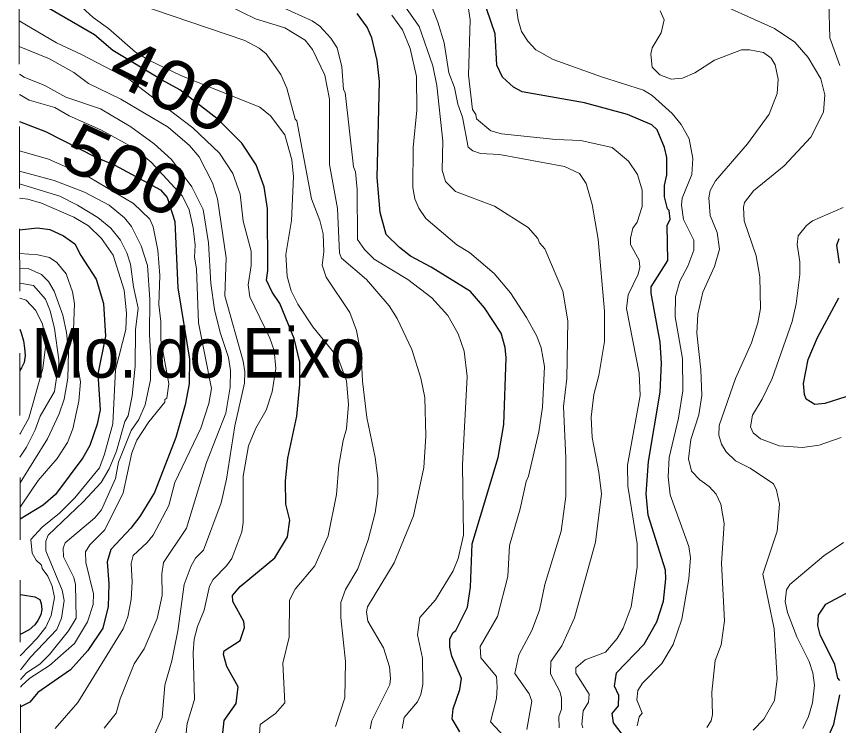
# Model space of a CAD drawing. Extents: x 474.5 to 500, y 7345.7 to 7373.4.
# Drawn here: x 474.522 to 475.844, y 7369.706 to 7370.847 of the extents above; entities that cross this region are included whole.
import ezdxf
from ezdxf.enums import TextEntityAlignment as Align

# ---------------------------------------------------------------- set-up
doc = ezdxf.new("R2010")
doc.units = 0
doc.header["$LTSCALE"] = 0.032
doc.linetypes.add('SHORT_DASHED', pattern=[2.7, 1.5, -1.2])
for name, color, linetype, lineweight in [('1', 7, 'Continuous', 25), ('2', 7, 'Continuous', 13), ('22', 7, 'SHORT_DASHED', 13)]:
    doc.layers.add(name, color=color, linetype=linetype, lineweight=lineweight)
doc.layers.add('61', color=7, linetype='Continuous')

msp = doc.modelspace()

# ---------------------------------------------------------------- linework, layer by layer
at = {"layer": '1'}
for points in [[(475.5426, 7370.4117), (475.5696, 7370.4544), (475.5681, 7370.5105), (475.5729, 7370.5208), (475.5713, 7370.5348), (475.5687, 7370.5375), (475.5641, 7370.5566), (475.5641, 7370.5748), (475.568, 7370.592), (475.568, 7370.62), (475.5639, 7370.6362), (475.5522, 7370.6644), (475.5439, 7370.6724), (475.5045, 7370.689), (475.4353, 7370.7078), (475.3351, 7370.7253), (475.321, 7370.7331), (475.3035, 7370.749), (475.2947, 7370.7685), (475.292, 7370.8186), (475.2434, 7370.9602)], [(474.8533, 7369.6894), (474.8564, 7369.7143), (474.8756, 7369.7417), (474.8785, 7369.7685), (474.8602, 7369.8014), (474.8549, 7369.8207), (474.8562, 7369.8265), (474.8819, 7369.843), (474.889, 7369.8642), (474.888, 7369.8738), (474.8701, 7369.906), (474.8697, 7369.9156), (474.8818, 7369.9299), (474.9376, 7369.976), (474.9579, 7370.01), (474.9618, 7370.0365), (474.9554, 7370.0626), (474.9548, 7370.0997), (474.9584, 7370.1361), (474.9731, 7370.204), (474.9777, 7370.2547), (474.9777, 7370.2908), (474.9685, 7370.3286), (474.9457, 7370.3849), (474.9334, 7370.4032), (474.9244, 7370.4227), (474.9265, 7370.4382), (474.9258, 7370.5381), (474.9204, 7370.5726), (474.9074, 7370.6083), (474.8846, 7370.6429), (474.8463, 7370.6808), (474.7848, 7370.729), (474.7566, 7370.7445), (474.6772, 7370.7919), (474.6478, 7370.817), (474.5266, 7370.8881)], [(475.2352, 7369.6964), (475.2227, 7369.7173), (475.2245, 7369.7333), (475.2351, 7369.7644), (475.2377, 7369.7818), (475.2223, 7369.8179), (475.2187, 7369.8323), (475.2187, 7369.8458), (475.224, 7369.856), (475.2283, 7369.8592), (475.2474, 7369.8967), (475.2522, 7369.929), (475.2546, 7369.9988), (475.2965, 7370.1376), (475.3055, 7370.1903), (475.3096, 7370.2976), (475.308, 7370.3144), (475.3016, 7370.3374), (475.2747, 7370.378), (475.2521, 7370.4046), (475.1889, 7370.4438), (475.1559, 7370.4613), (475.1378, 7370.475), (475.1164, 7370.496), (475.1069, 7370.5317), (475.1019, 7370.5877), (475.1061, 7370.7423), (475.1023, 7370.7758), (475.0933, 7370.8125), (475.0862, 7370.8298), (475.0701, 7370.8513)], [(474.527, 7370.6777), (474.5688, 7370.6619), (474.6497, 7370.6203), (474.6806, 7370.6076), (474.754, 7370.5678), (474.7644, 7370.5554), (474.7767, 7370.5171), (474.7814, 7370.4102), (474.8006, 7370.2956), (474.7997, 7370.2557), (474.7935, 7370.2222), (474.7784, 7370.1695), (474.7439, 7370.0813), (474.7204, 7370.0426), (474.7063, 7370.0238), (474.6739, 7369.9897), (474.6683, 7369.9698), (474.6706, 7369.9344), (474.6698, 7369.8977), (474.6609, 7369.8628), (474.6367, 7369.8272), (474.6091, 7369.7959), (474.5568, 7369.7594), (474.5437, 7369.7441), (474.5286, 7369.7362)], [(474.5273, 7370.5038), (474.5559, 7370.5067), (474.5759, 7370.5043), (474.5977, 7370.4941), (474.6162, 7370.4811), (474.6255, 7370.4622), (474.6506, 7370.4245), (474.662, 7370.3849), (474.6651, 7370.3327), (474.6531, 7370.2716), (474.657, 7370.214), (474.6519, 7370.1909), (474.6402, 7370.1565), (474.6287, 7370.1367), (474.585, 7370.0781), (474.565, 7370.061), (474.528, 7370.0382)], [(475.8455, 7370.4498), (475.841, 7370.4788), (475.845, 7370.4897)], [(475.5027, 7369.6832), (475.4818, 7369.7104), (475.4797, 7369.7257), (475.49, 7369.7381), (475.4907, 7369.7547), (475.4837, 7369.7697), (475.4866, 7369.7912), (475.5311, 7369.8372), (475.5516, 7369.8732), (475.5622, 7369.9063), (475.5664, 7369.9424), (475.5656, 7369.9562), (475.5378, 7370.0445), (475.5346, 7370.0792), (475.5385, 7370.1309), (475.5569, 7370.2423), (475.5593, 7370.2893), (475.5569, 7370.3227), (475.5426, 7370.4019), (475.5426, 7370.4117)], [(475.8555, 7370.2348), (475.822, 7370.2244), (475.8056, 7370.2229), (475.792, 7370.2311), (475.789, 7370.2389), (475.7875, 7370.2565), (475.7952, 7370.2952), (475.8097, 7370.3302), (475.844, 7370.394)], [(474.5276, 7370.3439), (474.5298, 7370.3379), (474.5338, 7370.3252), (474.5351, 7370.3131), (474.5361, 7370.3014), (474.5348, 7370.2904), (474.5304, 7370.2814), (474.5277, 7370.2773)], [(475.8457, 7369.7788), (475.8426, 7369.7826), (475.8376, 7369.8042), (475.8145, 7369.852), (475.8107, 7369.8674), (475.8115, 7369.8839), (475.8234, 7369.9013), (475.9077, 7369.9465)], [(474.5283, 7369.9171), (474.5318, 7369.9165), (474.5515, 7369.9132), (474.5599, 7369.9088), (474.5619, 7369.9025), (474.5629, 7369.8931), (474.5612, 7369.8841), (474.5565, 7369.8754), (474.5519, 7369.868), (474.5428, 7369.8603), (474.5291, 7369.853), (474.5284, 7369.8526)], [(475.8285, 7369.6916), (475.8362, 7369.7084), (475.8457, 7369.7557)]]:
    msp.add_lwpolyline(points, dxfattribs=at)
at = {"layer": '2'}
for points in [[(475.1774, 7370.8947), (475.1996, 7370.8375), (475.2098, 7370.8045), (475.2172, 7370.7561), (475.2266, 7370.7324), (475.2316, 7370.7057), (475.2395, 7370.6848), (475.2482, 7370.6368), (475.2558, 7370.6307), (475.268, 7370.6264), (475.2987, 7370.6247), (475.4035, 7370.6057), (475.4276, 7370.5944), (475.4379, 7370.578), (475.4476, 7370.5445), (475.4572, 7370.4886), (475.4675, 7370.3725), (475.4675, 7370.324), (475.4586, 7370.2692), (475.4506, 7370.2385), (475.4461, 7370.2021), (475.4476, 7370.1695), (475.4587, 7370.1137), (475.4627, 7370.0789), (475.4531, 7370.0012), (475.4191, 7369.8794), (475.3989, 7369.8343), (475.3812, 7369.8093), (475.3807, 7369.7896), (475.3956, 7369.7611), (475.3982, 7369.7507), (475.3982, 7369.7327), (475.3942, 7369.7209), (475.3949, 7369.7028)], [(475.3208, 7370.8982), (475.3287, 7370.8412), (475.3341, 7370.8224), (475.3442, 7370.8068), (475.3572, 7370.7933), (475.3849, 7370.7778), (475.4625, 7370.7496), (475.5301, 7370.7283), (475.5441, 7370.7197), (475.5764, 7370.6907), (475.5906, 7370.6732), (475.6038, 7370.6498), (475.6095, 7370.6182), (475.608, 7370.5926), (475.5924, 7370.5547), (475.5913, 7370.5433), (475.5948, 7370.52), (475.6111, 7370.4867), (475.6111, 7370.4709), (475.6014, 7370.4451), (475.5888, 7370.4211), (475.5815, 7370.3965), (475.5809, 7370.3637), (475.5929, 7370.2967), (475.5937, 7370.2446), (475.5864, 7370.2009), (475.5713, 7370.1376), (475.5697, 7370.1063), (475.5733, 7370.0771), (475.6031, 7369.994), (475.6056, 7369.9758), (475.6031, 7369.9422), (475.5921, 7369.8776), (475.5782, 7369.8369), (475.5597, 7369.806), (475.5284, 7369.7745), (475.5209, 7369.7625), (475.5195, 7369.7477), (475.5283, 7369.7261), (475.5235, 7369.7203), (475.5202, 7369.706)], [(475.8456, 7370.7678), (475.8297, 7370.8125), (475.8282, 7370.8693), (475.8256, 7370.8728), (475.8233, 7370.8942)], [(474.9125, 7369.684), (474.914, 7369.708), (474.9384, 7369.7256), (474.9537, 7369.7426), (474.9507, 7369.8065), (474.9604, 7369.8483), (474.9611, 7369.9079), (474.9701, 7369.9256), (475.0019, 7369.9632), (475.0233, 7370.0116), (475.0367, 7370.0781), (475.0406, 7370.1253), (475.0472, 7370.1647), (475.0527, 7370.1836), (475.0559, 7370.2225), (475.0526, 7370.2608), (475.0386, 7370.298), (474.9988, 7370.3474), (474.9743, 7370.384), (474.964, 7370.4057), (474.9575, 7370.4287), (474.9555, 7370.4638), (474.9643, 7370.5186), (474.9674, 7370.5889), (474.9649, 7370.616), (474.9537, 7370.6562), (474.9305, 7370.6871), (474.9134, 7370.7008), (474.7867, 7370.752), (474.7348, 7370.7765), (474.7135, 7370.7891), (474.6704, 7370.8276), (474.6458, 7370.8449), (474.6042, 7370.8834)], [(474.8188, 7370.8862), (474.9064, 7370.8431), (474.9536, 7370.8283), (474.9861, 7370.8086), (474.9982, 7370.7934), (475.018, 7370.7524), (475.0256, 7370.7139), (475.0257, 7370.6087), (475.0383, 7370.5381), (475.0416, 7370.4658), (475.0449, 7370.4579), (475.0848, 7370.4235), (475.1215, 7370.3812), (475.134, 7370.361), (475.158, 7370.3113), (475.1725, 7370.2648), (475.1787, 7370.2337), (475.1804, 7370.1719), (475.1771, 7370.1212), (475.1605, 7370.0435), (475.1293, 7369.9682), (475.0867, 7369.8973), (475.0847, 7369.889), (475.0869, 7369.8742), (475.1124, 7369.8313), (475.1221, 7369.8007), (475.1237, 7369.7821), (475.1222, 7369.7721), (475.0936, 7369.7142), (475.0911, 7369.7011)], [(475.629, 7370.8783), (475.7407, 7370.8273), (475.7737, 7370.8052), (475.795, 7370.7809), (475.8154, 7370.7466), (475.8218, 7370.7209), (475.8197, 7370.6926), (475.7992, 7370.6525), (475.7566, 7370.6066), (475.7073, 7370.5662), (475.6928, 7370.5478), (475.691, 7370.54), (475.6923, 7370.518), (475.7115, 7370.4618), (475.7172, 7370.428), (475.7181, 7370.3769), (475.7139, 7370.3538), (475.7041, 7370.3218), (475.6779, 7370.2645), (475.6519, 7370.1887), (475.6514, 7370.1734), (475.6556, 7370.1587), (475.6629, 7370.1464), (475.6782, 7370.1319), (475.7019, 7370.12), (475.7394, 7370.0952), (475.7443, 7370.0846), (475.7491, 7370.0623), (475.7453, 7370.0188), (475.7221, 7369.95), (475.7404, 7369.8619), (475.7451, 7369.7815), (475.7406, 7369.7463), (475.7238, 7369.7164), (475.7065, 7369.6991)], [(475.0349, 7369.7049), (475.0503, 7369.751), (475.0511, 7369.8092), (475.0435, 7369.8799), (475.0439, 7369.9042), (475.051, 7369.9249), (475.0708, 7369.9581), (475.0875, 7370.0049), (475.0991, 7370.0483), (475.1029, 7370.079), (475.103, 7370.1044), (475.099, 7370.1376), (475.0857, 7370.2018), (475.0783, 7370.26), (475.0766, 7370.302), (475.0686, 7370.3418), (475.0582, 7370.3706), (475.0202, 7370.4275), (475.0137, 7370.4466), (475.0161, 7370.4682), (475.0151, 7370.4969), (475.0097, 7370.5184), (474.9966, 7370.5532), (474.9729, 7370.6788), (474.9704, 7370.6814), (474.9568, 7370.7314), (474.9473, 7370.7535), (474.9237, 7370.7865), (474.9122, 7370.7956), (474.8895, 7370.8081), (474.714, 7370.8676)], [(475.3425, 7369.6999), (475.3505, 7369.7454), (475.3466, 7369.7572), (475.3232, 7369.7898), (475.3296, 7369.8201), (475.3509, 7369.8592), (475.363, 7369.8916), (475.3714, 7369.9329), (475.398, 7370.0188), (475.4053, 7370.0746), (475.4054, 7370.1362), (475.4014, 7370.2193), (475.4069, 7370.2645), (475.4086, 7370.3573), (475.4007, 7370.4049), (475.3714, 7370.4732), (475.3632, 7370.4826), (475.3606, 7370.4899), (475.3449, 7370.5074), (475.2907, 7370.5417), (475.2282, 7370.5653), (475.2118, 7370.5812), (475.2068, 7370.5995), (475.2076, 7370.646), (475.1979, 7370.7356), (475.1915, 7370.7675), (475.1696, 7370.8306), (475.1468, 7370.8633)], [(475.4327, 7369.7024), (475.4309, 7369.7077), (475.4331, 7369.7299), (475.442, 7369.7441), (475.4428, 7369.7566), (475.4215, 7369.7903), (475.4215, 7369.7991), (475.4367, 7369.8119), (475.4693, 7369.8241), (475.4877, 7369.8464), (475.4977, 7369.8627), (475.5105, 7369.8974), (475.5202, 7369.9612), (475.5202, 7369.9988), (475.505, 7370.0914), (475.5043, 7370.1252), (475.525, 7370.2373), (475.5234, 7370.2732), (475.5027, 7370.3769), (475.5058, 7370.3988), (475.5218, 7370.4325), (475.5242, 7370.4435), (475.5234, 7370.4548), (475.5091, 7370.48), (475.5091, 7370.4902), (475.5132, 7370.5063), (475.5203, 7370.5158), (475.5282, 7370.541), (475.5281, 7370.5672), (475.5207, 7370.5926), (475.506, 7370.6142), (475.4797, 7370.6361), (475.4295, 7370.6471), (475.3891, 7370.6489), (475.3019, 7370.6582), (475.285, 7370.663), (475.2619, 7370.6822), (475.2606, 7370.689), (475.2554, 7370.6969), (475.249, 7370.7526), (475.2514, 7370.8416), (475.2473, 7370.8697)], [(475.1421, 7369.7017), (475.1453, 7369.7193), (475.1667, 7369.7446), (475.1724, 7369.756), (475.1756, 7369.7725), (475.1748, 7369.8145), (475.1669, 7369.8524), (475.1707, 7369.8799), (475.196, 7369.9087), (475.2241, 7369.9552), (475.2324, 7369.9752), (475.241, 7370.0127), (475.2394, 7370.1258), (475.2466, 7370.2675), (475.2418, 7370.3083), (475.2325, 7370.3363), (475.2159, 7370.366), (475.1902, 7370.394), (475.1514, 7370.4239), (475.0973, 7370.4566), (475.0816, 7370.4722), (475.0703, 7370.4878), (475.0702, 7370.5684), (475.067, 7370.5968), (475.064, 7370.6049), (475.0504, 7370.7243), (475.048, 7370.7295), (475.0455, 7370.766), (475.0378, 7370.7965), (475.0274, 7370.812), (475.0101, 7370.831), (474.9975, 7370.8395), (474.948, 7370.8623)], [(475.632, 7369.703), (475.639, 7369.7136), (475.6414, 7369.7239), (475.6399, 7369.7602), (475.6455, 7369.811), (475.6551, 7369.8363), (475.6606, 7369.8747), (475.6559, 7369.9675), (475.6598, 7370.031), (475.6543, 7370.0621), (475.647, 7370.0783), (475.6359, 7370.091), (475.6206, 7370.1013), (475.6075, 7370.1153), (475.6024, 7370.135), (475.6064, 7370.1663), (475.6191, 7370.206), (475.6239, 7370.2373), (475.6223, 7370.2783), (475.616, 7370.3375), (475.6176, 7370.3677), (475.6255, 7370.4032), (475.6442, 7370.4447), (475.6526, 7370.4724), (475.6487, 7370.4993), (475.6375, 7370.5264), (475.6355, 7370.555), (475.6375, 7370.5667), (475.6461, 7370.5823), (475.6972, 7370.6421), (475.7324, 7370.6894), (475.7453, 7370.7227), (475.7467, 7370.7458), (475.7419, 7370.7691), (475.7355, 7370.7795), (475.7233, 7370.7888), (475.7008, 7370.7931), (475.688, 7370.7931), (475.6446, 7370.7763), (475.6125, 7370.7563), (475.5931, 7370.7475), (475.5747, 7370.746), (475.5564, 7370.7531), (475.5442, 7370.7654), (475.5418, 7370.7859), (475.5441, 7370.7961), (475.5585, 7370.8204), (475.5633, 7370.8415), (475.557, 7370.8559)], [(474.7943, 7369.6899), (474.7966, 7369.7095), (474.8086, 7369.748), (474.8063, 7369.8237), (474.8078, 7369.845), (474.8135, 7369.8658), (474.8242, 7369.8916), (474.8325, 7369.9302), (474.8382, 7369.9411), (474.8601, 7369.9629), (474.8686, 7369.9749), (474.8848, 7370.0177), (474.8869, 7370.033), (474.8869, 7370.1076), (474.8955, 7370.1563), (474.9073, 7370.1847), (474.9234, 7370.2137), (474.9332, 7370.2432), (474.9394, 7370.2804), (474.9363, 7370.3094), (474.9297, 7370.3291), (474.8972, 7370.3956), (474.8948, 7370.4152), (474.8995, 7370.4462), (474.8995, 7370.4692), (474.8868, 7370.5174), (474.8819, 7370.5607), (474.8698, 7370.5942), (474.8487, 7370.6269), (474.8057, 7370.6677), (474.7027, 7370.7459), (474.627, 7370.7858), (474.5868, 7370.8042), (474.5267, 7370.8396)], [(475.1258, 7370.8488), (475.1427, 7370.8252), (475.1554, 7370.7953), (475.1652, 7370.75), (475.1661, 7370.6962), (475.1597, 7370.6361), (475.1596, 7370.5717), (475.1629, 7370.5535), (475.169, 7370.5383), (475.1805, 7370.5216), (475.2302, 7370.4793), (475.2503, 7370.467), (475.2903, 7370.4334), (475.3162, 7370.402), (475.3422, 7370.3626), (475.3586, 7370.3327), (475.3656, 7370.3139), (475.3711, 7370.2835), (475.3678, 7370.2185), (475.3622, 7370.1786), (475.3456, 7370.1073), (475.3415, 7370.0988), (475.332, 7370.0547), (475.315, 7369.996), (475.312, 7369.9459), (475.2958, 7369.8815), (475.2676, 7369.8333), (475.2689, 7369.8153), (475.2937, 7369.785), (475.2952, 7369.7678), (475.2937, 7369.7499), (475.2841, 7369.7124), (475.3144, 7369.6799)], [(474.7425, 7369.6881), (474.7562, 7369.7192), (474.7608, 7369.771), (474.7719, 7369.8103), (474.7816, 7369.8584), (474.7919, 7369.9334), (474.803, 7369.9633), (474.8103, 7369.9754), (474.8229, 7369.9884), (474.8511, 7370.0645), (474.8597, 7370.1025), (474.8732, 7370.1882), (474.8886, 7370.2569), (474.8892, 7370.2751), (474.8868, 7370.2924), (474.8573, 7370.3972), (474.8596, 7370.4583), (474.8454, 7370.5535), (474.8374, 7370.5791), (474.8158, 7370.6208), (474.8004, 7370.6393), (474.7661, 7370.6688), (474.69, 7370.714), (474.6382, 7370.7387), (474.6145, 7370.7566), (474.5751, 7370.7786), (474.5268, 7370.7987)], [(474.5269, 7370.7542), (474.5345, 7370.749), (474.568, 7370.7355), (474.6018, 7370.7171), (474.6573, 7370.698), (474.706, 7370.6693), (474.7437, 7370.6419), (474.7713, 7370.6166), (474.804, 7370.5727), (474.8226, 7370.5364), (474.8309, 7370.4826), (474.8345, 7370.4175), (474.8405, 7370.3754), (474.8497, 7370.3383), (474.8629, 7370.2983), (474.8661, 7370.2771), (474.866, 7370.2506), (474.8588, 7370.2089), (474.8278, 7370.1296), (474.7957, 7370.0238), (474.7585, 7369.9685), (474.756, 7369.9501), (474.7567, 7369.9153), (474.7484, 7369.8783), (474.7273, 7369.8297), (474.7115, 7369.8057), (474.6889, 7369.7494), (474.6826, 7369.726), (474.6633, 7369.7022)], [(474.5845, 7369.7017), (474.621, 7369.7434), (474.694, 7369.8619), (474.7011, 7369.881), (474.7065, 7369.909), (474.7081, 7369.9374), (474.7066, 7369.9669), (474.7097, 7369.98), (474.7324, 7370.0006), (474.742, 7370.0126), (474.7671, 7370.06), (474.7766, 7370.0972), (474.8186, 7370.1846), (474.8316, 7370.2245), (474.8357, 7370.2485), (474.8151, 7370.3541), (474.8118, 7370.4408), (474.8087, 7370.4594), (474.8094, 7370.4791), (474.8063, 7370.507), (474.7999, 7370.536), (474.7894, 7370.5575), (474.7386, 7370.6124), (474.7126, 7370.6345), (474.6577, 7370.6646), (474.6067, 7370.6871), (474.5839, 7370.7004), (474.5429, 7370.7121), (474.5269, 7370.721)], [(474.5285, 7369.7682), (474.531, 7369.7705), (474.5439, 7369.7826), (474.5756, 7369.8031), (474.6156, 7369.8385), (474.6366, 7369.8731), (474.6458, 7369.9012), (474.6459, 7369.9181), (474.6339, 7369.9685), (474.6332, 7369.9856), (474.6401, 7369.9968), (474.6645, 7370.0208), (474.6939, 7370.0805), (474.7075, 7370.1447), (474.7158, 7370.1655), (474.7351, 7370.1946), (474.7605, 7370.2265), (474.7608, 7370.2305), (474.7639, 7370.2326), (474.7672, 7370.2561), (474.7544, 7370.3267), (474.7543, 7370.3562), (474.7512, 7370.3837), (474.7528, 7370.4303), (474.7495, 7370.4708), (474.7418, 7370.5086), (474.7367, 7370.521), (474.7103, 7370.546), (474.6378, 7370.589), (474.5738, 7370.6171), (474.5271, 7370.6309)], [(474.5272, 7370.5982), (474.5831, 7370.5827), (474.6318, 7370.564), (474.6714, 7370.5434), (474.6959, 7370.5228), (474.7073, 7370.5091), (474.7228, 7370.478), (474.7329, 7370.4463), (474.7368, 7370.3916), (474.7361, 7370.3359), (474.7385, 7370.2969), (474.7377, 7370.2624), (474.7289, 7370.2222), (474.7187, 7370.1984), (474.7068, 7370.181), (474.686, 7370.1298), (474.6812, 7370.1037), (474.6588, 7370.0531), (474.648, 7370.0406), (474.6005, 7370), (474.5974, 7369.9914), (474.5981, 7369.9779), (474.6146, 7369.9446), (474.6171, 7369.9334), (474.6184, 7369.8789), (474.606, 7369.8587), (474.5754, 7369.8204), (474.5597, 7369.8048), (474.5385, 7369.7911), (474.5285, 7369.7806)], [(474.5285, 7369.7958), (474.5312, 7369.7993), (474.5447, 7369.8165), (474.587, 7369.8605), (474.5944, 7369.8788), (474.5987, 7369.9075), (474.5957, 7369.9241), (474.5694, 7369.9874), (474.5694, 7370.003), (474.5732, 7370.0127), (474.6295, 7370.0659), (474.6586, 7370.0974), (474.6712, 7370.1193), (474.6832, 7370.1475), (474.6962, 7370.1955), (474.7019, 7370.2042), (474.7082, 7370.2365), (474.7129, 7370.2844), (474.7137, 7370.3425), (474.7177, 7370.3776), (474.7102, 7370.4117), (474.7058, 7370.4482), (474.6997, 7370.4667), (474.6896, 7370.4869), (474.6742, 7370.5064), (474.6533, 7370.5233), (474.6206, 7370.5433), (474.5919, 7370.5576), (474.5272, 7370.5774)], [(474.5272, 7370.5544), (474.5406, 7370.5528), (474.5627, 7370.5466), (474.6142, 7370.5241), (474.6379, 7370.5099), (474.6592, 7370.4894), (474.6777, 7370.4628), (474.6954, 7370.4068), (474.6993, 7370.3693), (474.6978, 7370.3434), (474.6816, 7370.2784), (474.6769, 7370.1916), (474.664, 7370.1428), (474.6558, 7370.1207), (474.6162, 7370.0726), (474.5916, 7370.0481), (474.5634, 7370.0253), (474.5454, 7370.0054), (474.5474, 7369.9836), (474.5541, 7369.9724), (474.5627, 7369.9643), (474.5638, 7369.9589), (474.5725, 7369.9466), (474.5796, 7369.9307), (474.5836, 7369.9122), (474.5782, 7369.8835), (474.5692, 7369.8643), (474.5557, 7369.8469), (474.5289, 7369.8191), (474.5284, 7369.8186)], [(475.8479, 7370.1695), (475.8129, 7370.1571), (475.786, 7370.1534), (475.7482, 7370.1562), (475.7183, 7370.1675), (475.7066, 7370.1771), (475.7022, 7370.1869), (475.7054, 7370.2057), (475.7211, 7370.2313), (475.737, 7370.2645), (475.7691, 7370.3559), (475.7755, 7370.3846), (475.7818, 7370.432), (475.7818, 7370.4519), (475.7772, 7370.4802), (475.7787, 7370.4937), (475.7922, 7370.5107), (475.8019, 7370.5178), (475.8511, 7370.5397)], [(474.528, 7370.0574), (474.5302, 7370.0606), (474.5572, 7370.1005), (474.5876, 7370.1359), (474.6044, 7370.1613), (474.6131, 7370.1837), (474.6227, 7370.2281), (474.6252, 7370.2593), (474.6135, 7370.3282), (474.6155, 7370.3849), (474.6124, 7370.4036), (474.6019, 7370.4328), (474.5873, 7370.4512), (474.5754, 7370.4589), (474.5568, 7370.4636), (474.5274, 7370.4656)], [(474.5274, 7370.442), (474.5413, 7370.4413), (474.5626, 7370.432), (474.5739, 7370.4207), (474.5831, 7370.4049), (474.5966, 7370.3666), (474.6028, 7370.3384), (474.606, 7370.3074), (474.6047, 7370.2649), (474.5987, 7370.231), (474.5908, 7370.2075), (474.5723, 7370.1674), (474.528, 7370.0968)], [(474.5279, 7370.1378), (474.5386, 7370.1542), (474.5524, 7370.1819), (474.5603, 7370.204), (474.5836, 7370.2438), (474.5875, 7370.273), (474.59, 7370.2765), (474.5901, 7370.2947), (474.5836, 7370.3447), (474.5765, 7370.3733), (474.5688, 7370.3921), (474.5495, 7370.4139), (474.5274, 7370.418)], [(474.5275, 7370.3935), (474.5379, 7370.3903), (474.5535, 7370.374), (474.5641, 7370.3518), (474.5701, 7370.324), (474.5644, 7370.2804), (474.5419, 7370.2006), (474.5287, 7370.1765), (474.5278, 7370.175), (474.5278, 7370.1749)], [(475.7865, 7369.7015), (475.7954, 7369.7209), (475.8017, 7369.7426), (475.805, 7369.7714), (475.8027, 7369.7909), (475.7966, 7369.8093), (475.7769, 7369.8491), (475.7615, 7369.8883), (475.758, 7369.9058), (475.7602, 7369.9243), (475.7654, 7369.9333), (475.8199, 7369.9793), (475.8518, 7370.0008)]]:
    msp.add_lwpolyline(points, dxfattribs=at)
at = {"layer": '22'}
msp.add_lwpolyline([(474.5381, 7364.3565), (474.5371, 7364.9213), (474.5361, 7365.4862), (474.5351, 7366.0511), (474.5341, 7366.616), (474.5331, 7367.1808), (474.5321, 7367.7457), (474.5311, 7368.3105), (474.5301, 7368.8754), (474.5291, 7369.4403), (474.5281, 7370.0051), (474.5272, 7370.57), (474.5262, 7371.1349), (474.5252, 7371.6997), (474.5242, 7372.2646), (474.5232, 7372.8295), (474.5222, 7373.3943)], dxfattribs=at)

# ---------------------------------------------------------------- texts
at = {"layer": '61', "width": 1.15}
for s, rotation, p in [('400', 333.773, (474.7566, 7370.7001)), ('500', 335.056, (474.6806, 7370.5635))]:
    msp.add_text(s, height=0.08, rotation=rotation, dxfattribs=at).set_placement(p, align=Align.CENTER)
at = {"layer": '61', "width": 0.95}
msp.add_text('Mo. do Eixo', height=0.08, dxfattribs=at).set_placement((474.8145, 7370.2658), align=Align.CENTER)

doc.saveas('drawing.dxf')
